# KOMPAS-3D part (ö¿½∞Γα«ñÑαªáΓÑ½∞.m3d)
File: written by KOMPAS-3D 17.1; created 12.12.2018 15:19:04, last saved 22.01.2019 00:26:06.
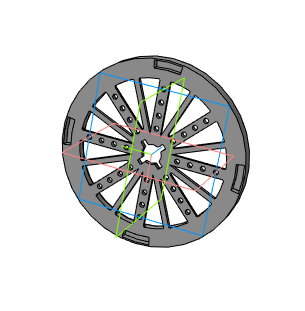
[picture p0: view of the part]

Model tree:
1. Тело
2. Операция выдавливания:1
     Расстояние 1 = 5
3. Перфорация
4. Операция выдавливания:2
     Расстояние 1 = 2
5. центральная крестовина
6. Вырезать элемент выдавливания:1
     Расстояние 1 = 4
7. Скругление:1
     Радиус = 2
8. Скругление:2
     Радиус = 1
9. Скругление:3
     Радиус = 1
10. Скругление:5
     Радиус = 1
11. Скругление:6
     Радиус = 1
12. Скругление:7
     Радиус = 1
13. Скругление:8
     Радиус = 1
14. Скругление:9
     Радиус = 1
15. Скругление:10
     Радиус = 1
16. Скругление:11
     Радиус = 1
17. Скругление:12
     Радиус = 1
18. Скругление:13
     Радиус = 1
19. Скругление:14
     Радиус = 1
20. Скругление:15
     Радиус = 1
21. Скругление:16
     Радиус = 1
22. Скругление:17
     Радиус = 1
23. Скругление:18
     Радиус = 1
24. Скругление:19
     Радиус = 0.5
25. Скругление:21
     Радиус = 0.5
26. Скругление:22
     Радиус = 0.5
27. Скругление:23
     Радиус = 0.5
28. Скругление:24
     Радиус = 0.5
29. Скругление:25
     Радиус = 0.5
30. Скругление:26
     Радиус = 0.5
31. Скругление:27
     Радиус = 0.5
32. Скругление:28
     Радиус = 0.5
33. Скругление:29
     Радиус = 0.5
34. Скругление:30
     Радиус = 0.5
35. Скругление:31
     Радиус = 0.5
36. Скругление:32
     Радиус = 0.4
37. Скругление:33
     Радиус = 0.5
38. Скругление:34
     Радиус = 0.5
39. Скругление:35
     Радиус = 0.5
40. Скругление:36
     Радиус = 0.5
41. Скругление:37
     Радиус = 0.5
42. Скругление:38
     Радиус = 0.5
43. Скругление:39
     Радиус = 0.5
44. Скругление:40
     Радиус = 0.5
45. Скругление:41
     Радиус = 0.5
46. Скругление:42
     Радиус = 0.5
47. Скругление:43
     Радиус = 0.5
48. Скругление:44
     Радиус = 0.5
49. Скругление:45
     Радиус = 0.5
50. Скругление:46
     Радиус = 0.5
51. Скругление:47
     Радиус = 0.5
52. Скругление:48
     Радиус = 0.5
53. Скругление:49
     Радиус = 0.5
54. Скругление:50
     Радиус = 0.5
55. Скругление:51
     Радиус = 0.5
56. Скругление:52
     Радиус = 0.5
57. Скругление:53
     Радиус = 0.5
58. Скругление:54
     Радиус = 0.5
59. Скругление:55
     Радиус = 0.5
60. Скругление:56
     Радиус = 0.5
61. Скругление:57
     Радиус = 0.5
62. Скругление:58
     Радиус = 0.5
63. Скругление:59
     Радиус = 0.5
64. Скругление:60
     Радиус = 0.5
65. Скругление:61
     Радиус = 0.5
66. Скругление:62
     Радиус = 0.5
67. Скругление:64
     Радиус = 0.5
68. Скругление:65
     Радиус = 0.5
69. Скругление:66
     Радиус = 0.4
70. Скругление:67
     Радиус = 0.4
71. Скругление:68
     Радиус = 0.4
72. Скругление:69
     Радиус = 0.4
73. Скругление:70
     Радиус = 0.4
74. Скругление:71
     Радиус = 0.4
75. Скругление:72
     Радиус = 0.4
76. Скругление:73
     Радиус = 0.3
77. Паз ограничителя фильтра
78. Вырезать элемент выдавливания:3
     Расстояние 1 = 3
79. Массив по концентрической сетке:1  (with: Вырезать элемент выдавливания:3, Скругление:1)  (4 pattern instances)
     Шаг 2 = 360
